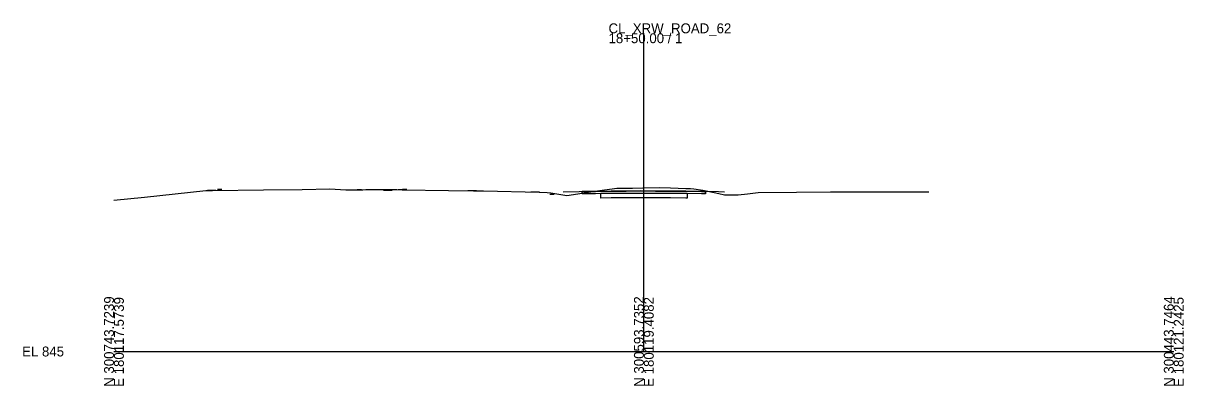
# Model space of a CAD drawing. Extents: x -26 to 303, y 490 to 4093.
# Drawn here: x -25.7 to 302.8, y 3490.3 to 3592.8 of the extents above; entities that cross this region are included whole.
import ezdxf

# ---------------------------------------------------------------- set-up
doc = ezdxf.new("R2010")
doc.units = 0
for name, color, linetype in [('CM_Corridor_Bottom_Mesh', 7, 'Continuous'), ('CM_Corridor_Top_Mesh', 7, 'Continuous'), ('Default', 7, 'Continuous'), ('GK_Cells', 7, 'Continuous'), ('MD_P_Subgrade', 7, 'Continuous'), ('MD_P_Surface_Aggregate_Base', 7, 'Continuous'), ('MD_P_Surface_Finished_Grade', 7, 'Continuous'), ('SV_X_Text_Comment', 7, 'Continuous'), ('SV_X_Text_Elevation', 7, 'Continuous'), ('SV_X_Text_Name', 7, 'Continuous'), ('XS_X_Ground_Line', 7, 'Continuous')]:
    doc.layers.add(name, color=color, linetype=linetype)

msp = doc.modelspace()

# ---------------------------------------------------------------- linework, layer by layer
at = {"layer": 'CM_Corridor_Bottom_Mesh'}
msp.add_lwpolyline([(172.81, 3545.06), (171.11, 3545.12), (167.48, 3545.22), (167.48, 3544.55), (166.36, 3544.58), (162.28, 3544.64), (161.86, 3544.65), (157.53, 3544.7), (153.32, 3544.73), (149.14, 3544.73), (144.96, 3544.72), (140.71, 3544.68), (137.83, 3544.64), (136.32, 3544.62), (132.5, 3544.55), (132.5, 3545.22), (131.72, 3545.2), (127.11, 3545.06)], dxfattribs=at)
at = {"layer": 'CM_Corridor_Top_Mesh'}
msp.add_lwpolyline([(172.81, 3545.06), (171.11, 3545.12), (167.48, 3545.22), (166.36, 3545.24), (161.86, 3545.32), (157.53, 3545.37), (153.32, 3545.39), (149.14, 3545.4), (144.96, 3545.38), (140.71, 3545.35), (136.32, 3545.29), (132.5, 3545.22), (131.72, 3545.2), (127.11, 3545.06)], dxfattribs=at)
at = {"layer": 'GK_Cells'}
for p, q in [((150, 3500), (150, 3590)), ((0, 3500), (150, 3500)), ((150, 3500), (300, 3500))]:
    msp.add_line(p, q, dxfattribs=at)
at = {"layer": 'MD_P_Subgrade'}
for points in [[(132.5, 3544.55), (132.5, 3545.22)], [(167.48, 3544.55), (167.48, 3545.22)], [(167.48, 3544.55), (166.36, 3544.58), (162.28, 3544.64), (162.28, 3543.4), (161.86, 3543.41), (157.53, 3543.44), (153.32, 3543.46), (149.14, 3543.46), (144.96, 3543.45), (140.71, 3543.43), (137.83, 3543.4), (137.83, 3544.64), (136.32, 3544.62), (132.5, 3544.55)]]:
    msp.add_lwpolyline(points, dxfattribs=at)
at = {"layer": 'MD_P_Surface_Aggregate_Base'}
msp.add_lwpolyline([(167.48, 3545.22), (167.48, 3544.55), (166.36, 3544.58), (161.86, 3544.65), (157.53, 3544.7), (153.32, 3544.73), (149.14, 3544.73), (144.96, 3544.72), (140.71, 3544.68), (136.32, 3544.62), (132.5, 3544.55), (132.5, 3545.22), (136.32, 3545.29), (140.71, 3545.35), (144.96, 3545.38), (149.14, 3545.4), (153.32, 3545.39), (157.53, 3545.37), (161.86, 3545.32), (166.36, 3545.24), (167.48, 3545.22)], dxfattribs=at)
at = {"layer": 'MD_P_Surface_Finished_Grade'}
for points in [[(132.5, 3545.22), (131.72, 3545.2), (127.11, 3545.06)], [(172.81, 3545.06), (171.11, 3545.12), (167.48, 3545.22)]]:
    msp.add_lwpolyline(points, dxfattribs=at)
at = {"layer": 'SV_X_Text_Comment'}
for points in [[(30.55, 3545.86), (29.35, 3545.86)], [(70.03, 3545.74), (68.83, 3545.74)], [(82.92, 3545.78), (81.72, 3545.78)]]:
    msp.add_lwpolyline(points, dxfattribs=at)
at = {"layer": 'SV_X_Text_Elevation'}
for points in [[(28.85, 3545.52), (27.65, 3545.52)], [(78.73, 3545.58), (77.53, 3545.58)], [(82.81, 3545.73), (81.61, 3545.73)], [(102.6, 3545.44), (101.4, 3545.44)], [(120.44, 3545.08), (119.24, 3545.08)], [(124.58, 3544.42), (123.38, 3544.42)]]:
    msp.add_lwpolyline(points, dxfattribs=at)
at = {"layer": 'SV_X_Text_Name'}
for points in [[(27.65, 3545.52), (26.45, 3545.52)], [(77.53, 3545.58), (76.33, 3545.58)], [(81.61, 3545.73), (80.41, 3545.73)], [(101.4, 3545.44), (100.2, 3545.44)], [(119.24, 3545.08), (118.04, 3545.08)]]:
    msp.add_lwpolyline(points, dxfattribs=at)
at = {"layer": 'XS_X_Ground_Line'}
msp.add_lwpolyline([(0, 3542.82), (8.6, 3543.64), (26.04, 3545.52), (27.92, 3545.55), (42.32, 3545.7), (53.24, 3545.84), (61.07, 3546), (65.62, 3545.76), (68.23, 3545.75), (70.4, 3545.71), (71.31, 3545.79), (77.06, 3545.78), (80.04, 3545.78), (81.62, 3545.74), (94.74, 3545.56), (101.79, 3545.43), (104.57, 3545.4), (120.33, 3545.08), (122.64, 3544.97), (123.62, 3544.83), (124.26, 3544.78), (128.18, 3544.15), (136.19, 3545.3), (138.83, 3545.7), (141.03, 3545.98), (142.33, 3546.15), (143, 3546.18), (144.03, 3546.24), (145, 3546.22), (146.78, 3546.17), (149.72, 3546.25), (154.39, 3546.4), (157.5, 3546.28), (161.92, 3546.09), (163.19, 3546.06), (164.1, 3546.04), (166.65, 3545.63), (168.11, 3545.34), (171.22, 3544.66), (172.78, 3544.3), (174.17, 3544.33), (176.72, 3544.3), (179.3, 3544.6), (182.36, 3545), (193.19, 3545.04), (202.81, 3545.16), (207.32, 3545.13), (230.71, 3545.2)], dxfattribs=at)

# ---------------------------------------------------------------- texts
at = {"layer": 'Default'}
msp.add_text('-', height=0.0001, dxfattribs=at).set_placement((0, 3500))
at = {"layer": 'GK_Cells'}
for s, p in [('CL_XRW_ROAD_62', (140, 3590)), ('18+50.00 / 1', (140, 3587.2)), ('EL 845', (-26, 3498.6))]:
    msp.add_text(s, height=2.8, dxfattribs=at).set_placement(p)
for s, p in [('N 300743.7239', (0, 3490)), ('N 300593.7352', (150, 3490)), ('N 300443.7464', (300, 3490)), ('E 180117.5739', (2.8, 3490)), ('E 180119.4082', (152.8, 3490)), ('E 180121.2425', (302.8, 3490))]:
    msp.add_text(s, height=2.8, rotation=90, dxfattribs=at).set_placement(p)

doc.saveas('drawing.dxf')
